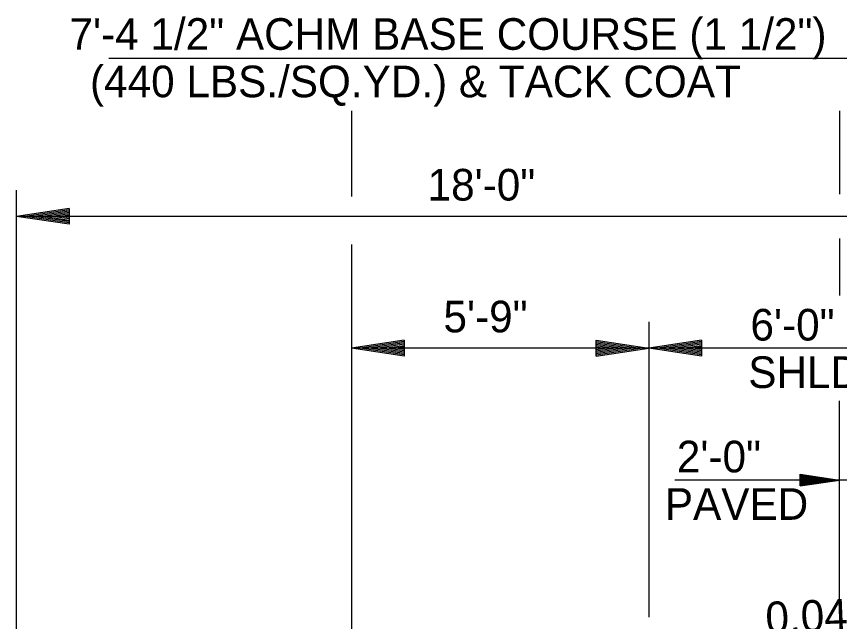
# Model space of a CAD drawing. Extents: x 2263886 to 2266026, y -3122850 to -3121850.
# Drawn here: x 2265466.57 to 2265482.19, y -3122285.15 to -3122273.67 of the extents above; entities that cross this region are included whole.
import ezdxf

# ---------------------------------------------------------------- set-up
doc = ezdxf.new("R2010")
doc.units = 0
doc.layers.add('R_Border Prem', color=7, linetype='Continuous')

msp = doc.modelspace()

# ---------------------------------------------------------------- linework, layer by layer
at = {"layer": 'R_Border Prem'}
for p, q in [((2265484.188, -3122274.466), (2265468.323, -3122274.466)), ((2265472.924, -3122275.462), (2265472.924, -3122277.084)), ((2265482.188, -3122275.462), (2265482.188, -3122277.042)), ((2265466.568, -3122288.062), (2265466.568, -3122276.962)), ((2265467.568, -3122277.312), (2265466.568, -3122277.462)), ((2265467.568, -3122277.337), (2265466.735, -3122277.462)), ((2265467.568, -3122277.363), (2265466.907, -3122277.462)), ((2265467.568, -3122277.388), (2265467.073, -3122277.462)), ((2265467.568, -3122277.414), (2265467.243, -3122277.462)), ((2265467.568, -3122277.439), (2265467.41, -3122277.462)), ((2265467.568, -3122277.312), (2265467.568, -3122277.612)), ((2265484.568, -3122277.462), (2265466.568, -3122277.462)), ((2265467.568, -3122277.612), (2265466.568, -3122277.462)), ((2265467.568, -3122277.587), (2265466.735, -3122277.462)), ((2265467.568, -3122277.562), (2265466.907, -3122277.462)), ((2265467.568, -3122277.537), (2265467.073, -3122277.462)), ((2265467.568, -3122277.511), (2265467.243, -3122277.462)), ((2265467.568, -3122277.486), (2265467.41, -3122277.462)), ((2265482.188, -3122277.882), (2265482.188, -3122278.962)), ((2265472.924, -3122277.994), (2265472.924, -3122286.473)), ((2265478.568, -3122279.462), (2265478.568, -3122285.062)), ((2265473.924, -3122279.812), (2265472.924, -3122279.962)), ((2265473.924, -3122279.837), (2265473.091, -3122279.962)), ((2265473.924, -3122279.863), (2265473.263, -3122279.962)), ((2265473.924, -3122279.888), (2265473.429, -3122279.962)), ((2265473.924, -3122279.914), (2265473.599, -3122279.962)), ((2265473.924, -3122279.939), (2265473.766, -3122279.962)), ((2265473.924, -3122279.812), (2265473.924, -3122280.112)), ((2265477.568, -3122279.812), (2265478.568, -3122279.962)), ((2265477.568, -3122280.112), (2265477.568, -3122279.812)), ((2265477.568, -3122279.837), (2265478.401, -3122279.962)), ((2265477.568, -3122279.863), (2265478.229, -3122279.962)), ((2265477.568, -3122279.888), (2265478.062, -3122279.962)), ((2265477.568, -3122279.913), (2265477.893, -3122279.962)), ((2265477.568, -3122279.939), (2265477.726, -3122279.962)), ((2265479.568, -3122279.812), (2265478.568, -3122279.962)), ((2265479.568, -3122279.837), (2265478.735, -3122279.962)), ((2265479.568, -3122279.863), (2265478.907, -3122279.962)), ((2265479.568, -3122279.888), (2265479.073, -3122279.962)), ((2265479.568, -3122279.914), (2265479.243, -3122279.962)), ((2265479.568, -3122279.939), (2265479.41, -3122279.962)), ((2265479.568, -3122279.812), (2265479.568, -3122280.112)), ((2265473.924, -3122280.112), (2265472.924, -3122279.962)), ((2265478.568, -3122279.962), (2265472.924, -3122279.962)), ((2265473.924, -3122280.087), (2265473.091, -3122279.962)), ((2265473.924, -3122280.062), (2265473.263, -3122279.962)), ((2265473.924, -3122280.037), (2265473.429, -3122279.962)), ((2265473.924, -3122280.011), (2265473.599, -3122279.962)), ((2265473.924, -3122279.986), (2265473.766, -3122279.962)), ((2265477.568, -3122280.112), (2265478.568, -3122279.962)), ((2265477.568, -3122280.011), (2265477.893, -3122279.962)), ((2265477.568, -3122280.062), (2265478.229, -3122279.962)), ((2265477.568, -3122280.087), (2265478.401, -3122279.962)), ((2265477.568, -3122280.037), (2265478.062, -3122279.962)), ((2265477.568, -3122279.986), (2265477.726, -3122279.962)), ((2265479.568, -3122280.112), (2265478.568, -3122279.962)), ((2265484.568, -3122279.962), (2265478.568, -3122279.962)), ((2265479.568, -3122280.087), (2265478.735, -3122279.962)), ((2265479.568, -3122280.062), (2265478.907, -3122279.962)), ((2265479.568, -3122280.037), (2265479.073, -3122279.962)), ((2265479.568, -3122280.011), (2265479.243, -3122279.962)), ((2265479.568, -3122279.986), (2265479.41, -3122279.962)), ((2265482.188, -3122284.997), (2265482.188, -3122280.962)), ((2265481.438, -3122282.35), (2265482.188, -3122282.462)), ((2265481.438, -3122282.575), (2265481.438, -3122282.35)), ((2265481.438, -3122282.368), (2265482.062, -3122282.462)), ((2265481.438, -3122282.388), (2265481.933, -3122282.462)), ((2265481.438, -3122282.406), (2265481.809, -3122282.462)), ((2265481.438, -3122282.425), (2265481.681, -3122282.462)), ((2265481.438, -3122282.445), (2265481.556, -3122282.462)), ((2265484.568, -3122282.462), (2265479.06, -3122282.462)), ((2265481.438, -3122282.575), (2265482.188, -3122282.462)), ((2265481.438, -3122282.499), (2265481.681, -3122282.462)), ((2265481.438, -3122282.537), (2265481.933, -3122282.462)), ((2265481.438, -3122282.556), (2265482.062, -3122282.462)), ((2265481.438, -3122282.518), (2265481.809, -3122282.462)), ((2265481.438, -3122282.48), (2265481.556, -3122282.462))]:
    msp.add_line(p, q, dxfattribs=at)

# ---------------------------------------------------------------- texts
for s, p in [('7\'-4 1/2" ACHM BASE COURSE (1 1/2")', (2265467.574, -3122274.303)), ('(440 LBS./SQ.YD.) & TACK COAT', (2265467.964, -3122275.203)), ('18\'-0"', (2265474.37, -3122277.162)), ('6\'-0"', (2265480.497, -3122279.817)), ('SHLD.', (2265480.456, -3122280.717)), ('2\'-0"', (2265479.1, -3122282.317)), ('PAVED', (2265478.873, -3122283.217))]:
    msp.add_text(s, height=0.6, dxfattribs=at).set_placement(p)
for s, rotation, p in [('5\'-9"', 0, (2265474.671, -3122279.662)), ("0.04'/'", 2.2906, (2265480.794, -3122285.374))]:
    msp.add_text(s, height=0.6, rotation=rotation, dxfattribs=at).set_placement(p)

doc.saveas('drawing.dxf')
